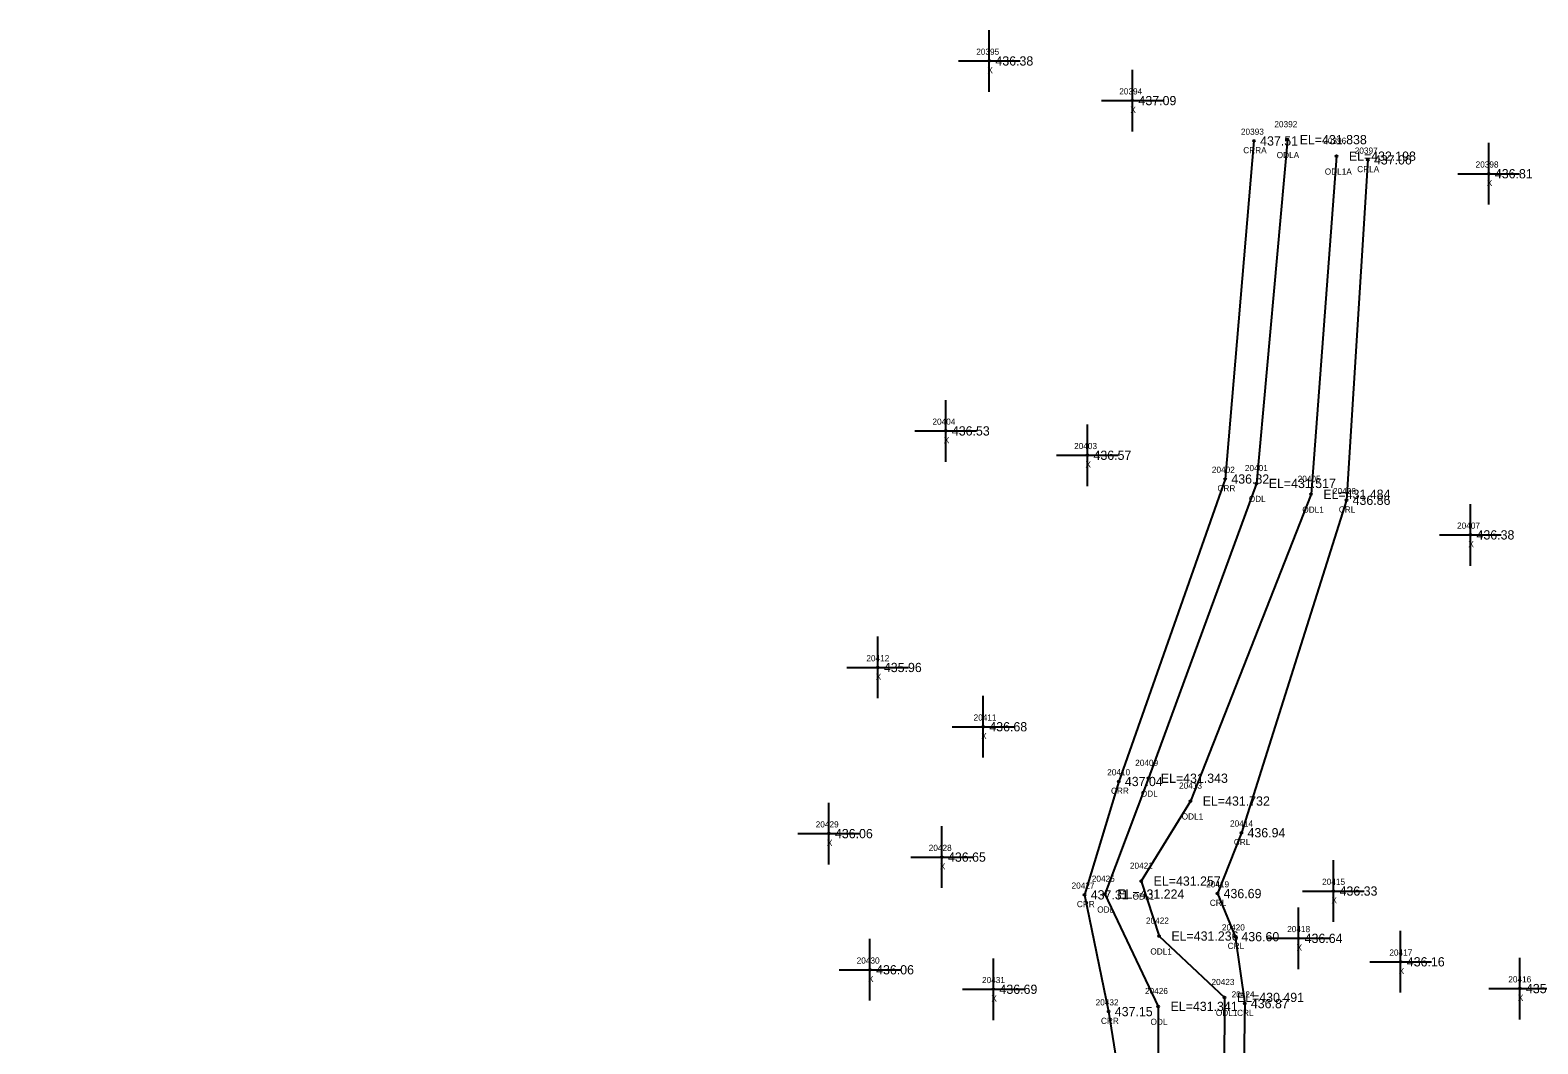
# Model space of a CAD drawing. Extents: x 1613836 to 1615109, y 777151 to 778248.
# Drawn here: x 1614435.8 to 1614680.1, y 778084 to 778248.4 of the extents above; entities that cross this region are included whole.
import ezdxf

# ---------------------------------------------------------------- set-up
doc = ezdxf.new("R2010")
doc.units = 0
for name, color, linetype in [('RD_EX_H2O', 7, 'Continuous'), ('RD_EX_H2O_txCode', 7, 'Continuous'), ('RD_EX_Misc', 7, 'Continuous'), ('RD_EX_Misc_txCode', 7, 'Continuous'), ('RD_EX_TX_H2O_ELEV', 7, 'Continuous'), ('RD_EX_TX_Misc_ELEV', 7, 'Continuous'), ('RD_SMD_Locator', 7, 'Continuous')]:
    doc.layers.add(name, color=color, linetype=linetype)

msp = doc.modelspace()

# ---------------------------------------------------------------- linework, layer by layer
at = {"layer": 'RD_EX_H2O'}
for points in [[(1614634.13, 778230.42), (1614629.46, 778175.6), (1614612.2, 778126.55), (1614606.67, 778108.17), (1614610.57, 778089.24), (1614615.98, 778055.09), (1614603.68, 778033.92), (1614586.84, 777977.49), (1614567.11, 777927.46), (1614559.23, 777908.74), (1614527.56, 777868.79), (1614521.38, 777849.92), (1614508, 777820.03), (1614493.75, 777779.64), (1614479.27, 777749.87), (1614469.02, 777727.63), (1614464.37, 777721.67), (1614444.52, 777689.77), (1614435.76, 777671.49)], [(1614639.54, 778230.63), (1614634.52, 778174.88), (1614617.02, 778127.08), (1614609.96, 778108.29), (1614618.6, 778090.08), (1614618.65, 778056.48), (1614610.43, 778030), (1614589.62, 777977.97), (1614569.81, 777927.89), (1614565.63, 777909.32), (1614534.03, 777865.55), (1614528.13, 777847.05), (1614516.47, 777815.91), (1614496.55, 777778.36), (1614481.67, 777748.03), (1614471.7, 777724.98), (1614468.53, 777719.48), (1614464.55, 777708.61), (1614459.06, 777697.65), (1614451.34, 777685.51), (1614441.64, 777670.36)], [(1614647.5, 778227.95), (1614643.37, 778173.13), (1614623.82, 778123.38), (1614615.86, 778110.4), (1614618.74, 778101.49), (1614629.36, 778091.54), (1614629.2, 778055.05), (1614623.38, 778037.62), (1614618.64, 778030.54), (1614608.82, 778009), (1614610.95, 778007.82), (1614616.5, 778011.66), (1614623.7, 778016.39), (1614633.68, 778018.1), (1614636.51, 778020.84), (1614637.06, 778026.36), (1614638.7, 778029.43), (1614642.25, 778034.18), (1614646.44, 778036.94), (1614653.41, 778045.28)], [(1614652.57, 778227.35), (1614649.11, 778172.15), (1614632.08, 778118.24), (1614628.2, 778108.38), (1614631.09, 778101.39), (1614632.62, 778090.53), (1614632.04, 778054.62), (1614632.37, 778039.71), (1614628.55, 778034.94), (1614622.29, 778030.08), (1614610.97, 778010.21)]]:
    msp.add_lwpolyline(points, dxfattribs=at)
at = {"layer": 'RD_EX_Misc'}
for p, q in [((1614591.22, 778238.39), (1614591.22, 778248.39)), ((1614586.22, 778243.39), (1614596.22, 778243.39)), ((1614614.41, 778231.96), (1614614.41, 778241.96)), ((1614609.41, 778236.96), (1614619.41, 778236.96)), ((1614672.17, 778220.1), (1614672.17, 778230.1)), ((1614667.17, 778225.1), (1614677.17, 778225.1)), ((1614584.16, 778178.4), (1614584.16, 778188.4)), ((1614579.16, 778183.4), (1614589.16, 778183.4)), ((1614607.12, 778174.45), (1614607.12, 778184.45)), ((1614602.12, 778179.45), (1614612.12, 778179.45)), ((1614669.2, 778161.54), (1614669.2, 778171.54)), ((1614664.2, 778166.54), (1614674.2, 778166.54)), ((1614573.14, 778140.04), (1614573.14, 778150.04)), ((1614568.14, 778145.04), (1614578.14, 778145.04)), ((1614590.23, 778130.43), (1614590.23, 778140.43)), ((1614585.23, 778135.43), (1614595.23, 778135.43)), ((1614565.21, 778113.1), (1614565.21, 778123.1)), ((1614583.53, 778109.29), (1614583.53, 778119.29)), ((1614560.21, 778118.1), (1614570.21, 778118.1)), ((1614578.53, 778114.29), (1614588.53, 778114.29)), ((1614647, 778103.79), (1614647, 778113.79)), ((1614642, 778108.79), (1614652, 778108.79)), ((1614641.34, 778096.12), (1614641.34, 778106.12)), ((1614657.9, 778092.31), (1614657.9, 778102.31)), ((1614571.88, 778091.02), (1614571.88, 778101.02)), ((1614636.34, 778101.12), (1614646.34, 778101.12)), ((1614591.88, 778087.86), (1614591.88, 778097.86)), ((1614652.9, 778097.31), (1614662.9, 778097.31)), ((1614677.21, 778087.97), (1614677.21, 778097.97)), ((1614566.88, 778096.02), (1614576.88, 778096.02)), ((1614586.88, 778092.86), (1614596.88, 778092.86)), ((1614672.21, 778092.97), (1614682.21, 778092.97))]:
    msp.add_line(p, q, dxfattribs=at)
at = {"layer": 'RD_SMD_Locator'}
for centre in [(1614591.22, 778243.39), (1614614.41, 778236.96), (1614634.13, 778230.42), (1614639.54, 778230.63), (1614647.5, 778227.95), (1614652.57, 778227.35), (1614672.17, 778225.1), (1614584.16, 778183.4), (1614607.12, 778179.45), (1614629.46, 778175.6), (1614634.52, 778174.88), (1614643.37, 778173.13), (1614649.11, 778172.15), (1614669.2, 778166.54), (1614573.14, 778145.04), (1614590.23, 778135.43), (1614612.2, 778126.55), (1614617.02, 778127.08), (1614623.82, 778123.38), (1614565.21, 778118.1), (1614632.08, 778118.24), (1614583.53, 778114.29), (1614615.86, 778110.4), (1614647, 778108.79), (1614606.67, 778108.17), (1614609.96, 778108.29), (1614628.2, 778108.38), (1614618.74, 778101.49), (1614631.09, 778101.39), (1614641.34, 778101.12), (1614657.9, 778097.31), (1614571.88, 778096.02), (1614591.88, 778092.86), (1614677.21, 778092.97), (1614610.57, 778089.24), (1614618.6, 778090.08), (1614629.36, 778091.54), (1614632.62, 778090.53)]:
    msp.add_circle(centre, 0.15, dxfattribs=at)

# ---------------------------------------------------------------- texts
at = {"layer": 'RD_EX_H2O_txCode'}
for s, p in [('20392', (1614637.43, 778232.63)), ('20393', (1614632.01, 778231.42)), ('CRRA', (1614632.39, 778228.42)), ('ODLA', (1614637.81, 778227.63)), ('20396', (1614645.36, 778229.95)), ('20397', (1614650.46, 778228.35)), ('CRLA', (1614650.86, 778225.35)), ('ODL1A', (1614645.6, 778224.95)), ('20402', (1614627.3, 778176.6)), ('20401', (1614632.65, 778176.88)), ('20405', (1614641.21, 778175.13)), ('CRR', (1614628.21, 778173.6)), ('ODL', (1614633.28, 778171.88)), ('20406', (1614646.93, 778173.15)), ('ODL1', (1614641.96, 778170.13)), ('CRL', (1614647.88, 778170.15)), ('20410', (1614610.33, 778127.55)), ('20409', (1614614.87, 778129.08)), ('20413', (1614621.98, 778125.38)), ('CRR', (1614610.95, 778124.55)), ('ODL', (1614615.78, 778124.08)), ('ODL1', (1614622.41, 778120.38)), ('20414', (1614630.25, 778119.24)), ('CRL', (1614630.86, 778116.24)), ('20425', (1614607.84, 778110.29)), ('20421', (1614614.02, 778112.4)), ('20427', (1614604.56, 778109.17)), ('20419', (1614626.37, 778109.38)), ('CRR', (1614605.42, 778106.17)), ('ODL1', (1614614.45, 778107.4)), ('CRL', (1614626.97, 778106.38)), ('ODL', (1614608.72, 778105.29)), ('20422', (1614616.62, 778103.49)), ('20420', (1614628.93, 778102.39)), ('ODL1', (1614617.33, 778098.49)), ('CRL', (1614629.86, 778099.39)), ('20423', (1614627.24, 778093.54)), ('20426', (1614616.46, 778092.08)), ('20424', (1614630.5, 778091.53)), ('20432', (1614608.46, 778090.24)), ('ODL1', (1614627.95, 778088.54)), ('CRL', (1614631.39, 778088.53)), ('CRR', (1614609.32, 778087.24)), ('ODL', (1614617.36, 778087.08))]:
    msp.add_text(s, height=1, dxfattribs=at).set_placement(p)
at = {"layer": 'RD_EX_Misc_txCode'}
for s, p in [('20395', (1614589.11, 778244.39)), ('X', (1614590.91, 778241.39)), ('20394', (1614612.29, 778237.96)), ('X', (1614614.09, 778234.96)), ('20398', (1614670.05, 778226.1)), ('X', (1614671.86, 778223.1)), ('20404', (1614582.01, 778184.4)), ('X', (1614583.85, 778181.4)), ('20403', (1614604.97, 778180.45)), ('X', (1614606.81, 778177.45)), ('20407', (1614667.04, 778167.54)), ('X', (1614668.88, 778164.54)), ('20412', (1614571.3, 778146.04)), ('X', (1614572.82, 778143.04)), ('20411', (1614588.68, 778136.43)), ('X', (1614589.91, 778133.43)), ('20429', (1614563.09, 778119.1)), ('X', (1614564.9, 778116.1)), ('20428', (1614581.41, 778115.29)), ('X', (1614583.21, 778112.29)), ('20415', (1614645.17, 778109.79)), ('X', (1614646.69, 778106.79)), ('20418', (1614639.51, 778102.12)), ('X', (1614641.03, 778099.12)), ('20417', (1614656.07, 778098.31)), ('20430', (1614569.73, 778097.02)), ('X', (1614571.57, 778094.02)), ('20431', (1614590.04, 778093.86)), ('X', (1614657.59, 778095.31)), ('20416', (1614675.35, 778093.97)), ('X', (1614591.56, 778090.86)), ('X', (1614676.89, 778090.97))]:
    msp.add_text(s, height=1, dxfattribs=at).set_placement(p)
at = {"layer": 'RD_EX_TX_H2O_ELEV'}
for s, p in [('437.51', (1614635.13, 778229.67)), ('EL=431.838', (1614641.54, 778229.88)), ('EL=432.198', (1614649.5, 778227.2)), ('437.06', (1614653.57, 778226.6)), ('436.82', (1614630.46, 778174.85)), ('EL=431.517', (1614636.52, 778174.13)), ('EL=431.484', (1614645.37, 778172.38)), ('436.86', (1614650.11, 778171.4)), ('437.04', (1614613.2, 778125.8)), ('EL=431.343', (1614619.02, 778126.33)), ('EL=431.732', (1614625.82, 778122.63)), ('436.94', (1614633.08, 778117.49)), ('437.31', (1614607.67, 778107.42)), ('EL=431.224', (1614611.96, 778107.54)), ('EL=431.257', (1614617.86, 778109.65)), ('436.69', (1614629.2, 778107.63)), ('EL=431.236', (1614620.74, 778100.74)), ('436.60', (1614632.09, 778100.64)), ('EL=430.491', (1614631.36, 778090.79)), ('437.15', (1614611.57, 778088.49)), ('EL=431.341', (1614620.6, 778089.33)), ('436.87', (1614633.62, 778089.78))]:
    msp.add_text(s, height=1.5, dxfattribs=at).set_placement(p)
at = {"layer": 'RD_EX_TX_Misc_ELEV'}
for s, p in [('436.38', (1614592.22, 778242.64)), ('437.09', (1614615.41, 778236.21)), ('436.81', (1614673.17, 778224.35)), ('436.53', (1614585.16, 778182.65)), ('436.57', (1614608.12, 778178.7)), ('436.38', (1614670.2, 778165.79)), ('435.96', (1614574.14, 778144.29)), ('436.68', (1614591.23, 778134.68)), ('436.06', (1614566.21, 778117.35)), ('436.65', (1614584.53, 778113.54)), ('436.33', (1614648, 778108.04)), ('436.64', (1614642.34, 778100.37)), ('436.06', (1614572.88, 778095.27)), ('436.16', (1614658.9, 778096.56)), ('436.69', (1614592.88, 778092.11)), ('435.75', (1614678.21, 778092.22))]:
    msp.add_text(s, height=1.5, dxfattribs=at).set_placement(p)

doc.saveas('drawing.dxf')
